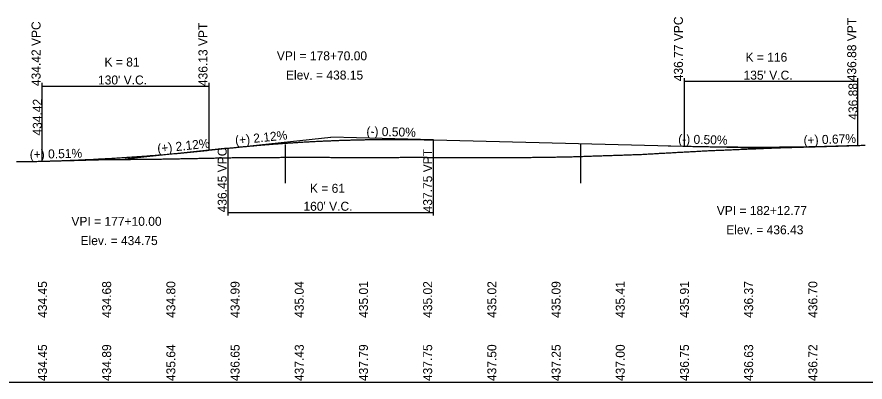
# Model space of a CAD drawing. Extents: x 1904865 to 1906752, y 1106408 to 1110518.
# Drawn here: x 1905711 to 1906371, y 1107658 to 1107942 of the extents above; entities that cross this region are included whole.
import ezdxf

# ---------------------------------------------------------------- set-up
doc = ezdxf.new("R2010")
doc.units = 0
for name, color, linetype in [('RD_DDB_GradeTX', 7, 'Continuous'), ('RD_DDB_Profile_EX', 7, 'Continuous'), ('RD_DDB_Profile_Lbl', 7, 'Continuous'), ('RD_DDB_Profile_PR', 7, 'Continuous'), ('RD_DDB_StripGrade', 7, 'Continuous'), ('RD_DDB_VCLbl', 7, 'Continuous'), ('RD_GPK_Profile_Cell', 7, 'Continuous'), ('RD_Sketch1', 7, 'Continuous')]:
    doc.layers.add(name, color=color, linetype=linetype)

msp = doc.modelspace()

# ---------------------------------------------------------------- linework, layer by layer
at = {"layer": 'RD_DDB_GradeTX'}
for p, q in [((1905875.45, 1107839.89), (1905955, 1107848.33)), ((1906034.98, 1107846.33), (1905955, 1107848.33)), ((1906217.8, 1107841.76), (1906297.77, 1107839.76)), ((1906365.27, 1107842.01), (1906297.77, 1107839.76)), ((1905874.56, 1107839.79), (1905795, 1107831.35)), ((1905730, 1107829.7), (1905795, 1107831.35))]:
    msp.add_line(p, q, dxfattribs=at)
at = {"layer": 'RD_DDB_Profile_EX'}
for points in [[(1906252.17, 1107838.06), (1906253.17, 1107838.11), (1906254.17, 1107838.15), (1906255.17, 1107838.19), (1906256.17, 1107838.23), (1906257.17, 1107838.27), (1906258.17, 1107838.31), (1906259.17, 1107838.36), (1906260.17, 1107838.4), (1906261.17, 1107838.44), (1906262.17, 1107838.48), (1906263.17, 1107838.52), (1906264.17, 1107838.56), (1906265.17, 1107838.61), (1906266.17, 1107838.65), (1906267.17, 1107838.69), (1906268.17, 1107838.73), (1906269.17, 1107838.77), (1906270.17, 1107838.81), (1906271.17, 1107838.85), (1906272.17, 1107838.9), (1906273.17, 1107838.94), (1906274.17, 1107838.98), (1906275.17, 1107839.02), (1906276.17, 1107839.06), (1906277.17, 1107839.1), (1906278.17, 1107839.15), (1906279.17, 1107839.19), (1906280.17, 1107839.23), (1906281.17, 1107839.27), (1906282.17, 1107839.31), (1906283.17, 1107839.35), (1906284.17, 1107839.4), (1906285.17, 1107839.44), (1906286.17, 1107839.48), (1906287.17, 1107839.52), (1906288.17, 1107839.56), (1906289.17, 1107839.6), (1906290.17, 1107839.65), (1906291.17, 1107839.69), (1906292.17, 1107839.73), (1906293.17, 1107839.77), (1906294.17, 1107839.81), (1906295.17, 1107839.85), (1906296.17, 1107839.9), (1906297.17, 1107839.94), (1906298.17, 1107839.98), (1906299.17, 1107840.02), (1906300.17, 1107840.06), (1906301.17, 1107840.1), (1906302.17, 1107840.15), (1906303.17, 1107840.18), (1906304.17, 1107840.21), (1906305.17, 1107840.24), (1906306.17, 1107840.27), (1906307.17, 1107840.3), (1906308.17, 1107840.33), (1906309.17, 1107840.36), (1906310.17, 1107840.39), (1906311.17, 1107840.42), (1906312.17, 1107840.45), (1906313.17, 1107840.47), (1906314.17, 1107840.5), (1906315.17, 1107840.53), (1906316.17, 1107840.56), (1906317.17, 1107840.59), (1906318.17, 1107840.62), (1906319.17, 1107840.65), (1906320.17, 1107840.68), (1906321.17, 1107840.71), (1906322.17, 1107840.74), (1906323.17, 1107840.76), (1906324.17, 1107840.79), (1906325.17, 1107840.82), (1906326.17, 1107840.85), (1906327.17, 1107840.88), (1906328.17, 1107840.91), (1906329.17, 1107840.94), (1906330.17, 1107840.97), (1906331.17, 1107841), (1906332.17, 1107841.03), (1906333.17, 1107841.05), (1906334.17, 1107841.08), (1906335.17, 1107841.11), (1906336.17, 1107841.14), (1906337.17, 1107841.17), (1906338.17, 1107841.2), (1906339.17, 1107841.23), (1906340.17, 1107841.26), (1906341.17, 1107841.29), (1906342.17, 1107841.32), (1906343.17, 1107841.34), (1906344.17, 1107841.37), (1906345.17, 1107841.4), (1906346.17, 1107841.43), (1906347.17, 1107841.46), (1906348.17, 1107841.49), (1906349.17, 1107841.52), (1906350.17, 1107841.55), (1906351.17, 1107841.58), (1906352.17, 1107841.61)], [(1906352.17, 1107841.61), (1906353.17, 1107841.63), (1906354.17, 1107841.66), (1906355.17, 1107841.69), (1906356.17, 1107841.72), (1906357.17, 1107841.75), (1906358.17, 1107841.79), (1906359.17, 1107841.82), (1906360.17, 1107841.85), (1906361.17, 1107841.88), (1906362.17, 1107841.91), (1906363.17, 1107841.94), (1906364.17, 1107841.97), (1906365.17, 1107842.01), (1906366.17, 1107842.04), (1906367.17, 1107842.07), (1906368.17, 1107842.1), (1906369.17, 1107842.13), (1906370.17, 1107842.16), (1906371.17, 1107842.19)], [(1906152.17, 1107833.53), (1906153.17, 1107833.57), (1906154.17, 1107833.6), (1906155.17, 1107833.63), (1906156.17, 1107833.67), (1906157.17, 1107833.7), (1906158.17, 1107833.73), (1906159.17, 1107833.77), (1906160.17, 1107833.8), (1906161.17, 1107833.83), (1906162.17, 1107833.87), (1906163.17, 1107833.9), (1906164.17, 1107833.93), (1906165.17, 1107833.97), (1906166.17, 1107834), (1906167.17, 1107834.04), (1906168.17, 1107834.07), (1906169.17, 1107834.1), (1906170.17, 1107834.14), (1906171.17, 1107834.17), (1906172.17, 1107834.2), (1906173.17, 1107834.24), (1906174.17, 1107834.27), (1906175.17, 1107834.3), (1906176.17, 1107834.34), (1906177.17, 1107834.37), (1906178.17, 1107834.4), (1906179.17, 1107834.44), (1906180.17, 1107834.47), (1906181.17, 1107834.51), (1906182.17, 1107834.54), (1906183.17, 1107834.57), (1906184.17, 1107834.61), (1906185.17, 1107834.64), (1906186.17, 1107834.67), (1906187.17, 1107834.71), (1906188.17, 1107834.74), (1906189.17, 1107834.77), (1906190.17, 1107834.81), (1906191.17, 1107834.84), (1906192.17, 1107834.88), (1906193.17, 1107834.91), (1906194.17, 1107834.94), (1906195.17, 1107834.97), (1906196.17, 1107835), (1906197.17, 1107835.05), (1906198.17, 1107835.11), (1906199.17, 1107835.17), (1906200.17, 1107835.22), (1906201.17, 1107835.28), (1906202.17, 1107835.34), (1906203.17, 1107835.4), (1906204.17, 1107835.45), (1906205.17, 1107835.51), (1906206.17, 1107835.57), (1906207.17, 1107835.62), (1906208.17, 1107835.68), (1906209.17, 1107835.74), (1906210.17, 1107835.8), (1906211.17, 1107835.85), (1906212.17, 1107835.91), (1906213.17, 1107835.97), (1906214.17, 1107836.02), (1906215.17, 1107836.08), (1906216.17, 1107836.14), (1906217.17, 1107836.19), (1906218.17, 1107836.25), (1906219.17, 1107836.3), (1906220.17, 1107836.36), (1906221.17, 1107836.41), (1906222.17, 1107836.47), (1906223.17, 1107836.52), (1906224.17, 1107836.58), (1906225.17, 1107836.63), (1906226.17, 1107836.68), (1906227.17, 1107836.74), (1906228.17, 1107836.79), (1906229.17, 1107836.85), (1906230.17, 1107836.9), (1906231.17, 1107836.96), (1906232.17, 1107837.01), (1906233.17, 1107837.07), (1906234.17, 1107837.12), (1906235.17, 1107837.18), (1906236.17, 1107837.23), (1906237.17, 1107837.29), (1906238.17, 1107837.34), (1906239.17, 1107837.39), (1906240.17, 1107837.45), (1906241.17, 1107837.5), (1906242.17, 1107837.56), (1906243.17, 1107837.61), (1906244.17, 1107837.67), (1906245.17, 1107837.72), (1906246.17, 1107837.78), (1906247.17, 1107837.83), (1906248.17, 1107837.89), (1906249.17, 1107837.94), (1906250.17, 1107837.98), (1906251.17, 1107838.02), (1906252.17, 1107838.06)], [(1905710.17, 1107829.35), (1905711.17, 1107829.36), (1905712.17, 1107829.37), (1905713.17, 1107829.38), (1905714.17, 1107829.4), (1905715.17, 1107829.41), (1905716.17, 1107829.42), (1905717.17, 1107829.43), (1905718.17, 1107829.44), (1905719.17, 1107829.45), (1905720.17, 1107829.47), (1905721.17, 1107829.48), (1905722.17, 1107829.49), (1905723.17, 1107829.51), (1905724.17, 1107829.54), (1905725.17, 1107829.57), (1905726.17, 1107829.59), (1905727.17, 1107829.62), (1905728.17, 1107829.65), (1905729.17, 1107829.67), (1905730.17, 1107829.7), (1905731.17, 1107829.73), (1905732.17, 1107829.76), (1905733.17, 1107829.78), (1905734.17, 1107829.81), (1905735.17, 1107829.84), (1905736.17, 1107829.86), (1905737.17, 1107829.89), (1905738.17, 1107829.92), (1905739.17, 1107829.95), (1905740.17, 1107829.97), (1905741.17, 1107830), (1905742.17, 1107830.03), (1905743.17, 1107830.05), (1905744.17, 1107830.08), (1905745.17, 1107830.11), (1905746.17, 1107830.14), (1905747.17, 1107830.16), (1905748.17, 1107830.19), (1905749.17, 1107830.22), (1905750.17, 1107830.24), (1905751.17, 1107830.27), (1905752.17, 1107830.3)], [(1905752.17, 1107830.3), (1905753.17, 1107830.33), (1905754.17, 1107830.35), (1905755.17, 1107830.38), (1905756.17, 1107830.41), (1905757.17, 1107830.43), (1905758.17, 1107830.46), (1905759.17, 1107830.49), (1905760.17, 1107830.52), (1905761.17, 1107830.54), (1905762.17, 1107830.57), (1905763.17, 1107830.6), (1905764.17, 1107830.62), (1905765.17, 1107830.65), (1905766.17, 1107830.68), (1905767.17, 1107830.71), (1905768.17, 1107830.73), (1905769.17, 1107830.76), (1905770.17, 1107830.79), (1905771.17, 1107830.82), (1905772.17, 1107830.85), (1905773.17, 1107830.88), (1905774.17, 1107830.9), (1905775.17, 1107830.91), (1905776.17, 1107830.92), (1905777.17, 1107830.93), (1905778.17, 1107830.94), (1905779.17, 1107830.95), (1905780.17, 1107830.96), (1905781.17, 1107830.97), (1905782.17, 1107830.98), (1905783.17, 1107830.99), (1905784.17, 1107831), (1905785.17, 1107831.02), (1905786.17, 1107831.03), (1905787.17, 1107831.04), (1905788.17, 1107831.05), (1905789.17, 1107831.06), (1905790.17, 1107831.07), (1905791.17, 1107831.08), (1905792.17, 1107831.09), (1905793.17, 1107831.1), (1905794.17, 1107831.11), (1905795.17, 1107831.12), (1905796.17, 1107831.13), (1905797.17, 1107831.14), (1905798.17, 1107831.15), (1905799.17, 1107831.16), (1905800.17, 1107831.17), (1905801.17, 1107831.19), (1905802.17, 1107831.2), (1905803.17, 1107831.21), (1905804.17, 1107831.22), (1905805.17, 1107831.23), (1905806.17, 1107831.24), (1905807.17, 1107831.25), (1905808.17, 1107831.26), (1905809.17, 1107831.27), (1905810.17, 1107831.28), (1905811.17, 1107831.29), (1905812.17, 1107831.3), (1905813.17, 1107831.31), (1905814.17, 1107831.32), (1905815.17, 1107831.33), (1905816.17, 1107831.34), (1905817.17, 1107831.36), (1905818.17, 1107831.37), (1905819.17, 1107831.38), (1905820.17, 1107831.39), (1905821.17, 1107831.4), (1905822.17, 1107831.41), (1905823.17, 1107831.42), (1905824.17, 1107831.43), (1905825.17, 1107831.44), (1905826.17, 1107831.45), (1905827.17, 1107831.47), (1905828.17, 1107831.49), (1905829.17, 1107831.51), (1905830.17, 1107831.53), (1905831.17, 1107831.55), (1905832.17, 1107831.57), (1905833.17, 1107831.59), (1905834.17, 1107831.61), (1905835.17, 1107831.63), (1905836.17, 1107831.65), (1905837.17, 1107831.67), (1905838.17, 1107831.69), (1905839.17, 1107831.71), (1905840.17, 1107831.72), (1905841.17, 1107831.74), (1905842.17, 1107831.76), (1905843.17, 1107831.78), (1905844.17, 1107831.8), (1905845.17, 1107831.82), (1905846.17, 1107831.84), (1905847.17, 1107831.86), (1905848.17, 1107831.88), (1905849.17, 1107831.9), (1905850.17, 1107831.92), (1905851.17, 1107831.94), (1905852.17, 1107831.96)], [(1905852.17, 1107831.96), (1905853.17, 1107831.98), (1905854.17, 1107832), (1905855.17, 1107832.02), (1905856.17, 1107832.04), (1905857.17, 1107832.06), (1905858.17, 1107832.08), (1905859.17, 1107832.1), (1905860.17, 1107832.12), (1905861.17, 1107832.14), (1905862.17, 1107832.16), (1905863.17, 1107832.18), (1905864.17, 1107832.2), (1905865.17, 1107832.22), (1905866.17, 1107832.24), (1905867.17, 1107832.26), (1905868.17, 1107832.28), (1905869.17, 1107832.3), (1905870.17, 1107832.32), (1905871.17, 1107832.34), (1905872.17, 1107832.36), (1905873.17, 1107832.38), (1905874.17, 1107832.4), (1905875.17, 1107832.42), (1905876.17, 1107832.44), (1905877.17, 1107832.46), (1905878.17, 1107832.48), (1905879.17, 1107832.49), (1905880.17, 1107832.49), (1905881.17, 1107832.5), (1905882.17, 1107832.51), (1905883.17, 1107832.51), (1905884.17, 1107832.52), (1905885.17, 1107832.53), (1905886.17, 1107832.53), (1905887.17, 1107832.54), (1905888.17, 1107832.54), (1905889.17, 1107832.55), (1905890.17, 1107832.56), (1905891.17, 1107832.56), (1905892.17, 1107832.57), (1905893.17, 1107832.58), (1905894.17, 1107832.58), (1905895.17, 1107832.59), (1905896.17, 1107832.6), (1905897.17, 1107832.6), (1905898.17, 1107832.61), (1905899.17, 1107832.62), (1905900.17, 1107832.62), (1905901.17, 1107832.63), (1905902.17, 1107832.64), (1905903.17, 1107832.64), (1905904.17, 1107832.65), (1905905.17, 1107832.66), (1905906.17, 1107832.66), (1905907.17, 1107832.67), (1905908.17, 1107832.68), (1905909.17, 1107832.68), (1905910.17, 1107832.69), (1905911.17, 1107832.7), (1905912.17, 1107832.7), (1905913.17, 1107832.71), (1905914.17, 1107832.72), (1905915.17, 1107832.72), (1905916.17, 1107832.73), (1905917.17, 1107832.73), (1905918.17, 1107832.74), (1905919.17, 1107832.75), (1905920.17, 1107832.75), (1905921.17, 1107832.76), (1905922.17, 1107832.77), (1905923.17, 1107832.77), (1905924.17, 1107832.78), (1905925.17, 1107832.79), (1905926.17, 1107832.79), (1905927.17, 1107832.8), (1905928.17, 1107832.81), (1905929.17, 1107832.81), (1905930.17, 1107832.82), (1905931.17, 1107832.82), (1905932.17, 1107832.81), (1905933.17, 1107832.81), (1905934.17, 1107832.8), (1905935.17, 1107832.8), (1905936.17, 1107832.8), (1905937.17, 1107832.79), (1905938.17, 1107832.79), (1905939.17, 1107832.79), (1905940.17, 1107832.78), (1905941.17, 1107832.78), (1905942.17, 1107832.77), (1905943.17, 1107832.77), (1905944.17, 1107832.77), (1905945.17, 1107832.76), (1905946.17, 1107832.76), (1905947.17, 1107832.75), (1905948.17, 1107832.75), (1905949.17, 1107832.75), (1905950.17, 1107832.74), (1905951.17, 1107832.74), (1905952.17, 1107832.73)], [(1905952.17, 1107832.73), (1905953.17, 1107832.73), (1905954.17, 1107832.73), (1905955.17, 1107832.72), (1905956.17, 1107832.72), (1905957.17, 1107832.72), (1905958.17, 1107832.71), (1905959.17, 1107832.71), (1905960.17, 1107832.7), (1905961.17, 1107832.69), (1905962.17, 1107832.69), (1905963.17, 1107832.69), (1905964.17, 1107832.69), (1905965.17, 1107832.68), (1905966.17, 1107832.68), (1905967.17, 1107832.68), (1905968.17, 1107832.68), (1905969.17, 1107832.67), (1905970.17, 1107832.67), (1905971.17, 1107832.67), (1905972.17, 1107832.67), (1905973.17, 1107832.66), (1905974.17, 1107832.66), (1905975.17, 1107832.66), (1905976.17, 1107832.66), (1905977.17, 1107832.65), (1905978.17, 1107832.65), (1905979.17, 1107832.65), (1905980.17, 1107832.65), (1905981.17, 1107832.65), (1905982.17, 1107832.64), (1905983.17, 1107832.64), (1905984.17, 1107832.64), (1905985.17, 1107832.64), (1905986.17, 1107832.63), (1905987.17, 1107832.63), (1905988.17, 1107832.63), (1905989.17, 1107832.62), (1905990.17, 1107832.62), (1905991.17, 1107832.63), (1905992.17, 1107832.64), (1905993.17, 1107832.64), (1905994.17, 1107832.65), (1905995.17, 1107832.65), (1905996.17, 1107832.66), (1905997.17, 1107832.66), (1905998.17, 1107832.67), (1905999.17, 1107832.67), (1906000.17, 1107832.68), (1906001.17, 1107832.68), (1906002.17, 1107832.69), (1906003.17, 1107832.69), (1906004.17, 1107832.7), (1906005.17, 1107832.7), (1906006.17, 1107832.71), (1906007.17, 1107832.71), (1906008.17, 1107832.72), (1906009.17, 1107832.73), (1906010.17, 1107832.73), (1906011.17, 1107832.74), (1906012.17, 1107832.74), (1906013.17, 1107832.75), (1906014.17, 1107832.75), (1906015.17, 1107832.76), (1906016.17, 1107832.76), (1906017.17, 1107832.77), (1906018.17, 1107832.77), (1906019.17, 1107832.78), (1906020.17, 1107832.78), (1906021.17, 1107832.77), (1906022.17, 1107832.77), (1906023.17, 1107832.76), (1906024.17, 1107832.76), (1906025.17, 1107832.75), (1906026.17, 1107832.75), (1906027.17, 1107832.74), (1906028.17, 1107832.74), (1906029.17, 1107832.73), (1906030.17, 1107832.73), (1906031.17, 1107832.72), (1906032.17, 1107832.72), (1906033.17, 1107832.71), (1906034.17, 1107832.71), (1906035.17, 1107832.7), (1906036.17, 1107832.7), (1906037.17, 1107832.69), (1906038.17, 1107832.69), (1906039.17, 1107832.68), (1906040.17, 1107832.68), (1906041.17, 1107832.67), (1906042.17, 1107832.67), (1906043.17, 1107832.66), (1906044.17, 1107832.66), (1906045.17, 1107832.65), (1906046.17, 1107832.65), (1906047.17, 1107832.64), (1906048.17, 1107832.64), (1906049.17, 1107832.63), (1906050.17, 1107832.63), (1906051.17, 1107832.63), (1906052.17, 1107832.63)], [(1906052.17, 1107832.63), (1906053.17, 1107832.63), (1906054.17, 1107832.64), (1906055.17, 1107832.64), (1906056.17, 1107832.64), (1906057.17, 1107832.64), (1906058.17, 1107832.65), (1906059.17, 1107832.65), (1906060.17, 1107832.65), (1906061.17, 1107832.65), (1906062.17, 1107832.66), (1906063.17, 1107832.66), (1906064.17, 1107832.66), (1906065.17, 1107832.66), (1906066.17, 1107832.67), (1906067.17, 1107832.67), (1906068.17, 1107832.67), (1906069.17, 1107832.67), (1906070.17, 1107832.68), (1906071.17, 1107832.68), (1906072.17, 1107832.68), (1906073.17, 1107832.68), (1906074.17, 1107832.68), (1906075.17, 1107832.69), (1906076.17, 1107832.69), (1906077.17, 1107832.69), (1906078.17, 1107832.69), (1906079.17, 1107832.7), (1906080.17, 1107832.7), (1906081.17, 1107832.7), (1906082.17, 1107832.7), (1906083.17, 1107832.7), (1906084.17, 1107832.7), (1906085.17, 1107832.7), (1906086.17, 1107832.7), (1906087.17, 1107832.7), (1906088.17, 1107832.7), (1906089.17, 1107832.7), (1906090.17, 1107832.7), (1906091.17, 1107832.7), (1906092.17, 1107832.7), (1906093.17, 1107832.7), (1906094.17, 1107832.7), (1906095.17, 1107832.7), (1906096.17, 1107832.7), (1906097.17, 1107832.7), (1906098.17, 1107832.7), (1906099.17, 1107832.7), (1906100.17, 1107832.7), (1906101.17, 1107832.69), (1906102.17, 1107832.69), (1906103.17, 1107832.69), (1906104.17, 1107832.69), (1906105.17, 1107832.69), (1906106.17, 1107832.69), (1906107.17, 1107832.69), (1906108.17, 1107832.69), (1906109.17, 1107832.69), (1906110.17, 1107832.71), (1906111.17, 1107832.72), (1906112.17, 1107832.74), (1906113.17, 1107832.75), (1906114.17, 1107832.77), (1906115.17, 1107832.78), (1906116.17, 1107832.79), (1906117.17, 1107832.81), (1906118.17, 1107832.82), (1906119.17, 1107832.83), (1906120.17, 1107832.85), (1906121.17, 1107832.86), (1906122.17, 1107832.87), (1906123.17, 1107832.89), (1906124.17, 1107832.9), (1906125.17, 1107832.91), (1906126.17, 1107832.93), (1906127.17, 1107832.94), (1906128.17, 1107832.96), (1906129.17, 1107832.97), (1906130.17, 1107832.98), (1906131.17, 1107833), (1906132.17, 1107833.01), (1906133.17, 1107833.02), (1906134.17, 1107833.04), (1906135.17, 1107833.05), (1906136.17, 1107833.06), (1906137.17, 1107833.08), (1906138.17, 1107833.09), (1906139.17, 1107833.11), (1906140.17, 1107833.13), (1906141.17, 1107833.16), (1906142.17, 1107833.2), (1906143.17, 1107833.23), (1906144.17, 1107833.26), (1906145.17, 1107833.3), (1906146.17, 1107833.33), (1906147.17, 1107833.36), (1906148.17, 1107833.4), (1906149.17, 1107833.43), (1906150.17, 1107833.46), (1906151.17, 1107833.5), (1906152.17, 1107833.53)]]:
    msp.add_lwpolyline(points, dxfattribs=at)
at = {"layer": 'RD_DDB_Profile_PR'}
for p, q in [((1906035, 1107846.33), (1906230.27, 1107841.44)), ((1905860, 1107838.25), (1905875, 1107839.84))]:
    msp.add_line(p, q, dxfattribs=at)
for points in [[(1905875, 1107839.84), (1905878.2, 1107840.17), (1905881.4, 1107840.5), (1905884.6, 1107840.82), (1905887.8, 1107841.13), (1905891, 1107841.43), (1905894.2, 1107841.73), (1905897.4, 1107842.01), (1905900.6, 1107842.29), (1905903.8, 1107842.55), (1905907, 1107842.81), (1905910.2, 1107843.07), (1905913.4, 1107843.31), (1905916.6, 1107843.54), (1905919.8, 1107843.77), (1905923, 1107843.99), (1905926.2, 1107844.2), (1905929.4, 1107844.4), (1905932.6, 1107844.59), (1905935.8, 1107844.77), (1905939, 1107844.95), (1905942.2, 1107845.12), (1905945.4, 1107845.28), (1905948.6, 1107845.43), (1905951.8, 1107845.57), (1905955, 1107845.7), (1905958.2, 1107845.83), (1905961.4, 1107845.95), (1905964.6, 1107846.06), (1905967.8, 1107846.16), (1905971, 1107846.25), (1905974.2, 1107846.33), (1905977.4, 1107846.41), (1905980.6, 1107846.47), (1905983.8, 1107846.53), (1905987, 1107846.58), (1905990.2, 1107846.62), (1905993.4, 1107846.66), (1905996.6, 1107846.68), (1905999.8, 1107846.7), (1906003, 1107846.71), (1906006.2, 1107846.71), (1906009.4, 1107846.7), (1906012.6, 1107846.68), (1906015.8, 1107846.65), (1906019, 1107846.62), (1906022.2, 1107846.58), (1906025.4, 1107846.53), (1906028.6, 1107846.47), (1906031.8, 1107846.4), (1906035, 1107846.33)], [(1906230.27, 1107841.44), (1906232.97, 1107841.38), (1906235.67, 1107841.32), (1906238.37, 1107841.26), (1906241.07, 1107841.2), (1906243.77, 1107841.15), (1906246.47, 1107841.1), (1906249.17, 1107841.05), (1906251.87, 1107841), (1906254.57, 1107840.96), (1906257.27, 1107840.93), (1906259.97, 1107840.89), (1906262.67, 1107840.86), (1906265.37, 1107840.83), (1906268.07, 1107840.81), (1906270.77, 1107840.79), (1906273.47, 1107840.77), (1906276.17, 1107840.75), (1906278.87, 1107840.74), (1906281.57, 1107840.73), (1906284.27, 1107840.72), (1906286.97, 1107840.72), (1906289.67, 1107840.72), (1906292.37, 1107840.73), (1906295.07, 1107840.73), (1906297.77, 1107840.74), (1906300.47, 1107840.75), (1906303.17, 1107840.77), (1906305.87, 1107840.79), (1906308.57, 1107840.81), (1906311.27, 1107840.84), (1906313.97, 1107840.87), (1906316.67, 1107840.9), (1906319.37, 1107840.93), (1906322.07, 1107840.97), (1906324.77, 1107841.01), (1906327.47, 1107841.06), (1906330.17, 1107841.1), (1906332.87, 1107841.15), (1906335.57, 1107841.21), (1906338.27, 1107841.27), (1906340.97, 1107841.33), (1906343.67, 1107841.39), (1906346.37, 1107841.46), (1906349.07, 1107841.53), (1906351.77, 1107841.6), (1906354.47, 1107841.67), (1906357.17, 1107841.75), (1906359.87, 1107841.84), (1906362.57, 1107841.92), (1906365.27, 1107842.01)], [(1905730, 1107829.7), (1905732.6, 1107829.77), (1905735.2, 1107829.84), (1905737.8, 1107829.91), (1905740.4, 1107830), (1905743, 1107830.08), (1905745.6, 1107830.17), (1905748.2, 1107830.26), (1905750.8, 1107830.36), (1905753.4, 1107830.46), (1905756, 1107830.57), (1905758.6, 1107830.68), (1905761.2, 1107830.79), (1905763.8, 1107830.91), (1905766.4, 1107831.04), (1905769, 1107831.16), (1905771.6, 1107831.29), (1905774.2, 1107831.43), (1905776.8, 1107831.57), (1905779.4, 1107831.71), (1905782, 1107831.86), (1905784.6, 1107832.01), (1905787.2, 1107832.17), (1905789.8, 1107832.33), (1905792.4, 1107832.49), (1905795, 1107832.66), (1905797.6, 1107832.84), (1905800.2, 1107833.01), (1905802.8, 1107833.19), (1905805.4, 1107833.38), (1905808, 1107833.57), (1905810.6, 1107833.76), (1905813.2, 1107833.96), (1905815.8, 1107834.17), (1905818.4, 1107834.37), (1905821, 1107834.58), (1905823.6, 1107834.8), (1905826.2, 1107835.02), (1905828.8, 1107835.24), (1905831.4, 1107835.47), (1905834, 1107835.7), (1905836.6, 1107835.94), (1905839.2, 1107836.18), (1905841.8, 1107836.42), (1905844.4, 1107836.67), (1905847, 1107836.92), (1905849.6, 1107837.18), (1905852.2, 1107837.44), (1905854.8, 1107837.71), (1905857.4, 1107837.97), (1905860, 1107838.25)]]:
    msp.add_spline(points, degree=3, dxfattribs=at)
at = {"layer": 'RD_DDB_VCLbl'}
for p, q in [((1906230.27, 1107894.51), (1906230.27, 1107841.44)), ((1906365.27, 1107894.51), (1906365.27, 1107842.01)), ((1905730, 1107890.75), (1905730, 1107829.7)), ((1905730, 1107888.25), (1905860, 1107888.25)), ((1905860, 1107890.75), (1905860, 1107838.25)), ((1906230.27, 1107892.01), (1906365.27, 1107892.01)), ((1906035, 1107787.34), (1906035, 1107846.33)), ((1905875, 1107787.34), (1905875, 1107839.84)), ((1905875, 1107789.84), (1906035, 1107789.84))]:
    msp.add_line(p, q, dxfattribs=at)
at = {"layer": 'RD_GPK_Profile_Cell'}
msp.add_line((1905252.2, 1107657.6), (1906752.2, 1107657.6), dxfattribs=at)
at = {"layer": 'RD_Sketch1'}
for p, q in [((1905919.84, 1107812.66), (1905919.84, 1107842.75)), ((1906149.84, 1107812.66), (1906149.84, 1107843.45))]:
    msp.add_line(p, q, dxfattribs=at)

# ---------------------------------------------------------------- texts
at = {"layer": 'RD_DDB_GradeTX'}
for s, rotation, p in [('(-) 0.50%', 358.5679, (1905982.73, 1107849.63)), ('(+) 2.12%', 6.05509, (1905820.32, 1107836.05)), ('(+) 2.12%', 6.05509, (1905880.88, 1107842.47)), ('(-) 0.50%', 358.5679, (1906225.53, 1107843.56)), ('(+) 0.67%', 1.91174, (1906323.37, 1107842.61)), ('(+) 0.51%', 1.45941, (1905720.65, 1107831.46))]:
    msp.add_text(s, height=7, rotation=rotation, dxfattribs=at).set_placement(p)
at = {"layer": 'RD_DDB_Profile_Lbl'}
for s, p in [('VPI = 178+70.00', (1905913.04, 1107908.33)), ('Elev. = 438.15', (1905920.15, 1107893.33)), ('VPI = 182+12.77', (1906255.65, 1107787.76)), ('VPI = 177+10.00', (1905753.04, 1107779.35)), ('Elev. = 436.43', (1906263.04, 1107772.76)), ('Elev. = 434.75', (1905760.15, 1107764.35))]:
    msp.add_text(s, height=7, dxfattribs=at).set_placement(p)
for s, p in [('436.88', (1906365.27, 1107862.01)), ('434.42', (1905730, 1107849.7))]:
    msp.add_text(s, height=7, rotation=90, dxfattribs=at).set_placement(p)
at = {"layer": 'RD_DDB_StripGrade'}
for s, p in [('436.77 VPC', (1906229.27, 1107892.01)), ('436.88 VPT', (1906364.27, 1107892.01)), ('434.42 VPC', (1905729, 1107888.25)), ('436.13 VPT', (1905859, 1107888.25)), ('436.45 VPC', (1905874, 1107789.84)), ('437.75 VPT', (1906034, 1107789.84)), ('434.45', (1905734, 1107707.6)), ('434.68', (1905784, 1107707.6)), ('434.80', (1905834, 1107707.6)), ('434.99', (1905884, 1107707.6)), ('435.04', (1905934, 1107707.6)), ('435.01', (1905984, 1107707.6)), ('435.02', (1906034, 1107707.6)), ('435.02', (1906084, 1107707.6)), ('435.09', (1906134, 1107707.6)), ('435.41', (1906184, 1107707.6)), ('435.91', (1906234, 1107707.6)), ('436.37', (1906284, 1107707.6)), ('436.70', (1906334, 1107707.6)), ('434.45', (1905734, 1107658.35)), ('434.89', (1905784, 1107658.35)), ('435.64', (1905834, 1107658.35)), ('436.65', (1905884, 1107658.35)), ('437.43', (1905934, 1107658.35)), ('437.79', (1905984, 1107658.35)), ('437.75', (1906034, 1107658.35)), ('437.50', (1906084, 1107658.35)), ('437.25', (1906134, 1107658.35)), ('437.00', (1906184, 1107658.35)), ('436.75', (1906234, 1107658.35)), ('436.63', (1906284, 1107658.35)), ('436.72', (1906334, 1107658.35))]:
    msp.add_text(s, height=7, rotation=90, dxfattribs=at).set_placement(p)
at = {"layer": 'RD_DDB_VCLbl'}
for s, p in [('K = 116', (1906278.05, 1107907.26)), ('K = 81', (1905778.81, 1107903.5)), ("135' V.C.", (1906276.52, 1107893.26)), ("130' V.C.", (1905773.75, 1107889.5)), ('K = 61', (1905938.81, 1107805.09)), ("160' V.C.", (1905933.75, 1107791.09))]:
    msp.add_text(s, height=7, dxfattribs=at).set_placement(p)

doc.saveas('drawing.dxf')
